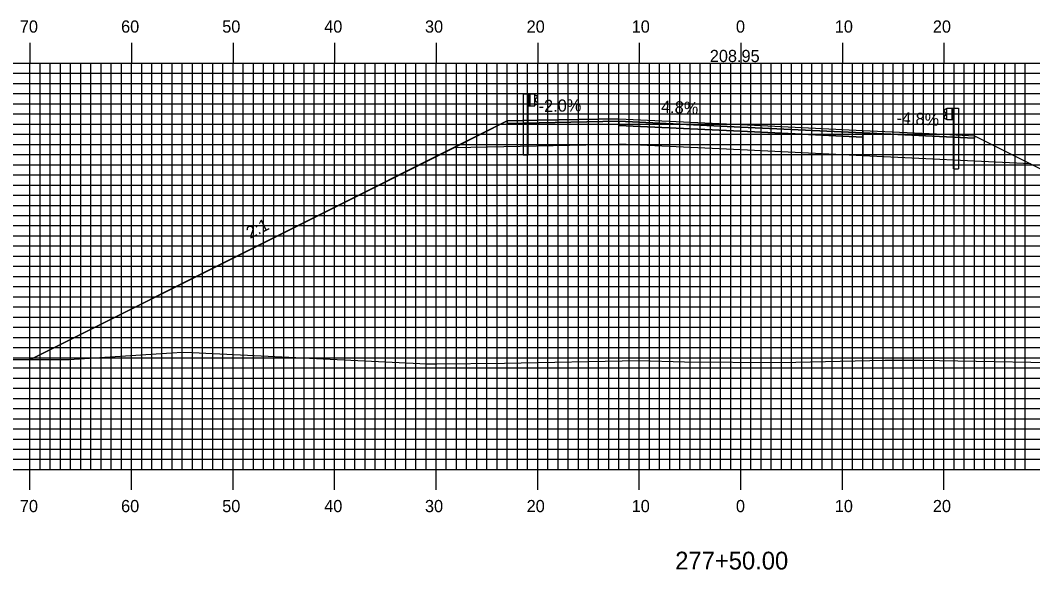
# Model space of a CAD drawing. Extents: x 1810193 to 1810536, y 442591 to 442811.
# Drawn here: x 1810287.9 to 1810387.6, y 442658.8 to 442712.9 of the extents above; entities that cross this region are included whole.
import ezdxf

# ---------------------------------------------------------------- set-up
doc = ezdxf.new("R2010")
doc.units = 0
for name, color, linetype in [('ANNOTATION', 7, 'Continuous'), ('D_Guardrail_Beam_Lt', 7, 'Continuous'), ('D_Guardrail_Beam_Rt', 7, 'Continuous'), ('D_Roadway_Centerline', 7, 'Continuous'), ('D_Roadway_Centerline_Text', 7, 'Continuous'), ('D_Roadway_Edge_Shoulder', 7, 'Continuous'), ('D_Roadway_Edge_TW', 7, 'Continuous'), ('D_Roadway_Pavement', 7, 'Continuous'), ('D_Roadway_SlopeLines', 7, 'Continuous'), ('D_Roadway_SubGrade', 7, 'Continuous'), ('H_V ANNOTATION', 7, 'Continuous'), ('MAJOR', 7, 'Continuous'), ('MINOR', 7, 'Continuous'), ('S_Roadway_Centerline', 7, 'Continuous')]:
    doc.layers.add(name, color=color, linetype=linetype)

msp = doc.modelspace()

# ---------------------------------------------------------------- linework, layer by layer
at = {"layer": 'D_Guardrail_Beam_Lt'}
for p, q in [((1810337.434, 442705.62), (1810337.434, 442699.62)), ((1810337.905, 442705.62), (1810337.434, 442705.62)), ((1810338.593, 442705.62), (1810337.905, 442705.62)), ((1810337.905, 442705.62), (1810337.905, 442704.453)), ((1810337.968, 442705.62), (1810337.968, 442704.453)), ((1810338.072, 442705.62), (1810338.072, 442704.453)), ((1810338.593, 442704.453), (1810338.593, 442705.62)), ((1810338.593, 442705.536), (1810338.667, 442705.522)), ((1810338.597, 442705.071), (1810338.597, 442705.001)), ((1810338.826, 442705.272), (1810338.631, 442705.136)), ((1810338.631, 442704.937), (1810338.826, 442704.801)), ((1810338.683, 442705.515), (1810338.826, 442705.415)), ((1810337.905, 442704.453), (1810338.593, 442704.453)), ((1810337.926, 442699.62), (1810337.926, 442704.453)), ((1810338.667, 442704.551), (1810338.593, 442704.536)), ((1810338.826, 442704.657), (1810338.683, 442704.557)), ((1810337.926, 442699.62), (1810337.434, 442699.62))]:
    msp.add_line(p, q, dxfattribs=at)
for centre, major_axis, start_param, end_param in [((1810338.676, 442705.071), (-0.0789, 0), 5.323254, 6.283185), ((1810338.676, 442705.001), (-0.0789, 0), 6.283185, 7.243116), ((1810338.659, 442705.481), (0.0417, 0), 0.959931, 1.376053), ((1810338.776, 442705.343), (0.0877, 0), 5.323254, 7.243116), ((1810338.776, 442704.729), (0.0877, 0), 5.323254, 7.243116), ((1810338.659, 442704.591), (0.0417, 0), 4.907132, 5.323254)]:
    msp.add_ellipse(centre, major_axis=major_axis, ratio=0.995501, start_param=start_param, end_param=end_param, dxfattribs=at)
at = {"layer": 'D_Guardrail_Beam_Rt'}
for p, q in [((1810379.044, 442704.139), (1810378.901, 442704.039)), ((1810378.901, 442703.896), (1810379.096, 442703.76)), ((1810379.134, 442704.16), (1810379.06, 442704.146)), ((1810379.134, 442704.244), (1810379.822, 442704.244)), ((1810379.134, 442703.077), (1810379.134, 442704.244)), ((1810379.655, 442704.244), (1810379.655, 442703.077)), ((1810379.759, 442704.244), (1810379.759, 442703.077)), ((1810379.822, 442704.244), (1810380.293, 442704.244)), ((1810379.822, 442704.244), (1810379.822, 442703.077)), ((1810380.293, 442704.244), (1810380.293, 442698.244)), ((1810379.096, 442703.561), (1810378.901, 442703.425)), ((1810378.901, 442703.281), (1810379.044, 442703.181)), ((1810379.06, 442703.175), (1810379.134, 442703.16)), ((1810379.13, 442703.695), (1810379.13, 442703.625)), ((1810379.822, 442703.077), (1810379.134, 442703.077)), ((1810379.801, 442698.244), (1810379.801, 442703.077)), ((1810379.801, 442698.244), (1810380.293, 442698.244))]:
    msp.add_line(p, q, dxfattribs=at)
for centre, major_axis, start_param, end_param in [((1810378.951, 442703.967), (-0.0877, 0), 5.323254, 7.243116), ((1810379.068, 442704.105), (-0.0417, 0), 4.907132, 5.323254), ((1810379.051, 442703.695), (0.0789, 0), 0, 0.959931), ((1810378.951, 442703.353), (-0.0877, 0), 5.323254, 7.243116), ((1810379.068, 442703.215), (-0.0417, 0), 0.959931, 1.376053), ((1810379.051, 442703.625), (0.0789, 0), 5.323254, 6.283185)]:
    msp.add_ellipse(centre, major_axis=major_axis, ratio=0.995501, start_param=start_param, end_param=end_param, dxfattribs=at)
at = {"layer": 'D_Roadway_Centerline'}
msp.add_lwpolyline([(1810288.916, 442679.503), (1810330.655, 442700.372), (1810335.863, 442702.976), (1810338.863, 442703.036), (1810346.863, 442703.196), (1810358.863, 442702.62), (1810370.863, 442702.044), (1810378.863, 442701.66), (1810381.863, 442701.516), (1810387.395, 442698.751), (1810427.355, 442678.771)], dxfattribs=at)
at = {"layer": 'D_Roadway_Edge_Shoulder'}
for points in [[(1810346.863, 442703.196), (1810338.863, 442703.036), (1810338.863, 442703.036), (1810335.863, 442702.976), (1810335.863, 442702.726), (1810346.863, 442702.946)], [(1810370.863, 442702.044), (1810378.863, 442701.66), (1810378.863, 442701.66), (1810381.863, 442701.516), (1810381.863, 442701.266), (1810370.863, 442701.794)]]:
    msp.add_lwpolyline(points, close=True, dxfattribs=at)
at = {"layer": 'D_Roadway_Edge_TW'}
msp.add_lwpolyline([(1810346.863, 442702.946), (1810346.863, 442703.196), (1810358.863, 442702.62), (1810370.863, 442702.044), (1810370.863, 442701.794), (1810358.863, 442702.37)], close=True, dxfattribs=at)
at = {"layer": 'D_Roadway_Pavement'}
msp.add_lwpolyline([(1810346.863, 442702.53), (1810346.863, 442702.946), (1810358.863, 442702.37), (1810370.863, 442701.794), (1810370.863, 442701.378), (1810358.863, 442701.954)], close=True, dxfattribs=at)
for points in [[(1810346.863, 442702.946), (1810346.863, 442702.53)], [(1810370.863, 442701.794), (1810370.863, 442701.378)]]:
    msp.add_lwpolyline(points, dxfattribs=at)
at = {"layer": 'D_Roadway_SlopeLines'}
for points in [[(1810335.863, 442702.976), (1810288.916, 442679.503)], [(1810381.863, 442701.516), (1810427.355, 442678.771)]]:
    msp.add_lwpolyline(points, dxfattribs=at)
at = {"layer": 'D_Roadway_SubGrade'}
for points in [[(1810346.863, 442702.53), (1810346.863, 442702.946), (1810335.863, 442702.726), (1810335.863, 442702.976), (1810330.655, 442700.372), (1810346.863, 442700.696)], [(1810346.863, 442700.696), (1810346.863, 442702.946), (1810346.863, 442702.53), (1810358.863, 442701.954), (1810370.863, 442701.378), (1810370.863, 442701.794), (1810370.863, 442699.544), (1810358.863, 442700.12)], [(1810370.863, 442701.378), (1810370.863, 442701.794), (1810381.863, 442701.266), (1810381.863, 442701.516), (1810387.395, 442698.751), (1810370.863, 442699.544)]]:
    msp.add_lwpolyline(points, close=True, dxfattribs=at)
at = {"layer": 'MAJOR'}
for p, q in [((1810288.863, 442710.669), (1810288.863, 442708.665)), ((1810298.863, 442710.669), (1810298.863, 442708.665)), ((1810308.863, 442710.669), (1810308.863, 442708.665)), ((1810318.863, 442710.669), (1810318.863, 442708.665)), ((1810328.863, 442710.669), (1810328.863, 442708.665)), ((1810338.863, 442710.669), (1810338.863, 442708.665)), ((1810348.863, 442710.669), (1810348.863, 442708.665)), ((1810358.863, 442710.669), (1810358.863, 442708.665)), ((1810368.863, 442710.669), (1810368.863, 442708.665)), ((1810378.863, 442710.669), (1810378.863, 442708.665)), ((1810218.863, 442708.665), (1810498.863, 442708.665)), ((1810218.863, 442708.665), (1810498.863, 442708.665)), ((1810288.863, 442668.665), (1810288.863, 442708.665)), ((1810298.863, 442668.665), (1810298.863, 442708.665)), ((1810308.863, 442668.665), (1810308.863, 442708.665)), ((1810318.863, 442668.665), (1810318.863, 442708.665)), ((1810328.863, 442668.665), (1810328.863, 442708.665)), ((1810338.863, 442668.665), (1810338.863, 442708.665)), ((1810348.863, 442668.665), (1810348.863, 442708.665)), ((1810358.863, 442668.665), (1810358.863, 442708.665)), ((1810368.863, 442668.665), (1810368.863, 442708.665)), ((1810378.863, 442668.665), (1810378.863, 442708.665)), ((1810218.863, 442703.665), (1810498.863, 442703.665)), ((1810218.863, 442698.665), (1810498.863, 442698.665)), ((1810218.863, 442693.665), (1810498.863, 442693.665)), ((1810218.863, 442688.665), (1810498.863, 442688.665)), ((1810218.863, 442683.665), (1810498.863, 442683.665)), ((1810218.863, 442678.665), (1810498.863, 442678.665)), ((1810218.863, 442673.665), (1810498.863, 442673.665)), ((1810218.863, 442668.665), (1810498.863, 442668.665)), ((1810218.863, 442668.665), (1810498.863, 442668.665)), ((1810288.863, 442666.661), (1810288.863, 442668.665)), ((1810298.863, 442666.661), (1810298.863, 442668.665)), ((1810308.863, 442666.661), (1810308.863, 442668.665)), ((1810318.863, 442666.661), (1810318.863, 442668.665)), ((1810328.863, 442666.661), (1810328.863, 442668.665)), ((1810338.863, 442666.661), (1810338.863, 442668.665)), ((1810348.863, 442666.661), (1810348.863, 442668.665)), ((1810358.863, 442666.661), (1810358.863, 442668.665)), ((1810368.863, 442666.661), (1810368.863, 442668.665)), ((1810378.863, 442666.661), (1810378.863, 442668.665))]:
    msp.add_line(p, q, dxfattribs=at)
at = {"layer": 'MINOR'}
for p, q in [((1810289.863, 442668.665), (1810289.863, 442708.665)), ((1810290.863, 442668.665), (1810290.863, 442708.665)), ((1810291.863, 442668.665), (1810291.863, 442708.665)), ((1810292.863, 442668.665), (1810292.863, 442708.665)), ((1810293.863, 442668.665), (1810293.863, 442708.665)), ((1810294.863, 442668.665), (1810294.863, 442708.665)), ((1810295.863, 442668.665), (1810295.863, 442708.665)), ((1810296.863, 442668.665), (1810296.863, 442708.665)), ((1810297.863, 442668.665), (1810297.863, 442708.665)), ((1810299.863, 442668.665), (1810299.863, 442708.665)), ((1810300.863, 442668.665), (1810300.863, 442708.665)), ((1810301.863, 442668.665), (1810301.863, 442708.665)), ((1810302.863, 442668.665), (1810302.863, 442708.665)), ((1810303.863, 442668.665), (1810303.863, 442708.665)), ((1810304.863, 442668.665), (1810304.863, 442708.665)), ((1810305.863, 442668.665), (1810305.863, 442708.665)), ((1810306.863, 442668.665), (1810306.863, 442708.665)), ((1810307.863, 442668.665), (1810307.863, 442708.665)), ((1810309.863, 442668.665), (1810309.863, 442708.665)), ((1810310.863, 442668.665), (1810310.863, 442708.665)), ((1810311.863, 442668.665), (1810311.863, 442708.665)), ((1810312.863, 442668.665), (1810312.863, 442708.665)), ((1810313.863, 442668.665), (1810313.863, 442708.665)), ((1810314.863, 442668.665), (1810314.863, 442708.665)), ((1810315.863, 442668.665), (1810315.863, 442708.665)), ((1810316.863, 442668.665), (1810316.863, 442708.665)), ((1810317.863, 442668.665), (1810317.863, 442708.665)), ((1810319.863, 442668.665), (1810319.863, 442708.665)), ((1810320.863, 442668.665), (1810320.863, 442708.665)), ((1810321.863, 442668.665), (1810321.863, 442708.665)), ((1810322.863, 442668.665), (1810322.863, 442708.665)), ((1810323.863, 442668.665), (1810323.863, 442708.665)), ((1810324.863, 442668.665), (1810324.863, 442708.665)), ((1810325.863, 442668.665), (1810325.863, 442708.665)), ((1810326.863, 442668.665), (1810326.863, 442708.665)), ((1810327.863, 442668.665), (1810327.863, 442708.665)), ((1810329.863, 442668.665), (1810329.863, 442708.665)), ((1810330.863, 442668.665), (1810330.863, 442708.665)), ((1810331.863, 442668.665), (1810331.863, 442708.665)), ((1810332.863, 442668.665), (1810332.863, 442708.665)), ((1810333.863, 442668.665), (1810333.863, 442708.665)), ((1810334.863, 442668.665), (1810334.863, 442708.665)), ((1810335.863, 442668.665), (1810335.863, 442708.665)), ((1810336.863, 442668.665), (1810336.863, 442708.665)), ((1810337.863, 442668.665), (1810337.863, 442708.665)), ((1810339.863, 442668.665), (1810339.863, 442708.665)), ((1810340.863, 442668.665), (1810340.863, 442708.665)), ((1810341.863, 442668.665), (1810341.863, 442708.665)), ((1810342.863, 442668.665), (1810342.863, 442708.665)), ((1810343.863, 442668.665), (1810343.863, 442708.665)), ((1810344.863, 442668.665), (1810344.863, 442708.665)), ((1810345.863, 442668.665), (1810345.863, 442708.665)), ((1810346.863, 442668.665), (1810346.863, 442708.665)), ((1810347.863, 442668.665), (1810347.863, 442708.665)), ((1810349.863, 442668.665), (1810349.863, 442708.665)), ((1810350.863, 442668.665), (1810350.863, 442708.665)), ((1810351.863, 442668.665), (1810351.863, 442708.665)), ((1810352.863, 442668.665), (1810352.863, 442708.665)), ((1810353.863, 442668.665), (1810353.863, 442708.665)), ((1810354.863, 442668.665), (1810354.863, 442708.665)), ((1810355.863, 442668.665), (1810355.863, 442708.665)), ((1810356.863, 442668.665), (1810356.863, 442708.665)), ((1810357.863, 442668.665), (1810357.863, 442708.665)), ((1810359.863, 442668.665), (1810359.863, 442708.665)), ((1810360.863, 442668.665), (1810360.863, 442708.665)), ((1810361.863, 442668.665), (1810361.863, 442708.665)), ((1810362.863, 442668.665), (1810362.863, 442708.665)), ((1810363.863, 442668.665), (1810363.863, 442708.665)), ((1810364.863, 442668.665), (1810364.863, 442708.665)), ((1810365.863, 442668.665), (1810365.863, 442708.665)), ((1810366.863, 442668.665), (1810366.863, 442708.665)), ((1810367.863, 442668.665), (1810367.863, 442708.665)), ((1810369.863, 442668.665), (1810369.863, 442708.665)), ((1810370.863, 442668.665), (1810370.863, 442708.665)), ((1810371.863, 442668.665), (1810371.863, 442708.665)), ((1810372.863, 442668.665), (1810372.863, 442708.665)), ((1810373.863, 442668.665), (1810373.863, 442708.665)), ((1810374.863, 442668.665), (1810374.863, 442708.665)), ((1810375.863, 442668.665), (1810375.863, 442708.665)), ((1810376.863, 442668.665), (1810376.863, 442708.665)), ((1810377.863, 442668.665), (1810377.863, 442708.665)), ((1810379.863, 442668.665), (1810379.863, 442708.665)), ((1810380.863, 442668.665), (1810380.863, 442708.665)), ((1810381.863, 442668.665), (1810381.863, 442708.665)), ((1810382.863, 442668.665), (1810382.863, 442708.665)), ((1810383.863, 442668.665), (1810383.863, 442708.665)), ((1810384.863, 442668.665), (1810384.863, 442708.665)), ((1810385.863, 442668.665), (1810385.863, 442708.665)), ((1810386.863, 442668.665), (1810386.863, 442708.665)), ((1810218.863, 442707.665), (1810498.863, 442707.665)), ((1810218.863, 442706.665), (1810498.863, 442706.665)), ((1810218.863, 442705.665), (1810498.863, 442705.665)), ((1810218.863, 442704.665), (1810498.863, 442704.665)), ((1810218.863, 442702.665), (1810498.863, 442702.665)), ((1810218.863, 442701.665), (1810498.863, 442701.665)), ((1810218.863, 442700.665), (1810498.863, 442700.665)), ((1810218.863, 442699.665), (1810498.863, 442699.665)), ((1810218.863, 442697.665), (1810498.863, 442697.665)), ((1810218.863, 442696.665), (1810498.863, 442696.665)), ((1810218.863, 442695.665), (1810498.863, 442695.665)), ((1810218.863, 442694.665), (1810498.863, 442694.665)), ((1810218.863, 442692.665), (1810498.863, 442692.665)), ((1810218.863, 442691.665), (1810498.863, 442691.665)), ((1810218.863, 442690.665), (1810498.863, 442690.665)), ((1810218.863, 442689.665), (1810498.863, 442689.665)), ((1810218.863, 442687.665), (1810498.863, 442687.665)), ((1810218.863, 442686.665), (1810498.863, 442686.665)), ((1810218.863, 442685.665), (1810498.863, 442685.665)), ((1810218.863, 442684.665), (1810498.863, 442684.665)), ((1810218.863, 442682.665), (1810498.863, 442682.665)), ((1810218.863, 442681.665), (1810498.863, 442681.665)), ((1810218.863, 442680.665), (1810498.863, 442680.665)), ((1810218.863, 442679.665), (1810498.863, 442679.665)), ((1810218.863, 442677.665), (1810498.863, 442677.665)), ((1810218.863, 442676.665), (1810498.863, 442676.665)), ((1810218.863, 442675.665), (1810498.863, 442675.665)), ((1810218.863, 442674.665), (1810498.863, 442674.665)), ((1810218.863, 442672.665), (1810498.863, 442672.665)), ((1810218.863, 442671.665), (1810498.863, 442671.665)), ((1810218.863, 442670.665), (1810498.863, 442670.665)), ((1810218.863, 442669.665), (1810498.863, 442669.665))]:
    msp.add_line(p, q, dxfattribs=at)
at = {"layer": 'S_Roadway_Centerline'}
msp.add_lwpolyline([(1810218.863, 442679.332), (1810223.523, 442679.457), (1810232.549, 442679.313), (1810235.549, 442679.241), (1810238.398, 442679.29), (1810255.314, 442679.168), (1810259.948, 442679.217), (1810269.89, 442679.529), (1810279.08, 442679.526), (1810281.568, 442679.506), (1810292.735, 442679.501), (1810302.786, 442680.159), (1810303.87, 442680.202), (1810304.849, 442680.189), (1810327.958, 442679.074), (1810328.938, 442679.078), (1810335.583, 442679.137), (1810348.835, 442679.401), (1810353.3, 442679.268), (1810362.8, 442679.181), (1810373.055, 442679.415), (1810374.702, 442679.438), (1810376.616, 442679.441), (1810394.657, 442679.113)], dxfattribs=at)

# ---------------------------------------------------------------- texts
at = {"layer": 'ANNOTATION'}
for s, rotation, p in [('-2.0%', 1.14576, (1810338.97, 442703.839)), ('4.8%', 357.25191, (1810350.993, 442703.8)), ('-4.8%', 357.25191, (1810374.172, 442702.688)), ('2:1', 26.56505, (1810310.535, 442691.348))]:
    msp.add_text(s, height=1.2, rotation=rotation, dxfattribs=at).set_placement(p)
at = {"layer": 'D_Roadway_Centerline'}
for s, p in [('C', (1810358.858, 442702.62)), ('L', (1810358.863, 442702.613))]:
    msp.add_text(s, height=0.0146, dxfattribs=at).set_placement(p)
at = {"layer": 'D_Roadway_Centerline_Text'}
msp.add_text('208.95', height=1.2, dxfattribs=at).set_placement((1810355.808, 442708.768))
at = {"layer": 'H_V ANNOTATION'}
for s, height, p in [('70', 1.2, (1810287.868, 442711.665)), ('60', 1.2, (1810297.836, 442711.665)), ('50', 1.2, (1810307.793, 442711.665)), ('40', 1.2, (1810317.836, 442711.665)), ('30', 1.2, (1810327.761, 442711.665)), ('20', 1.2, (1810337.771, 442711.665)), ('10', 1.2, (1810348.114, 442711.665)), ('0', 1.2, (1810358.382, 442711.665)), ('10', 1.2, (1810368.114, 442711.665)), ('20', 1.2, (1810377.771, 442711.665)), ('70', 1.2, (1810287.868, 442664.465)), ('60', 1.2, (1810297.836, 442664.465)), ('50', 1.2, (1810307.793, 442664.465)), ('40', 1.2, (1810317.836, 442664.465)), ('30', 1.2, (1810327.761, 442664.465)), ('20', 1.2, (1810337.771, 442664.465)), ('10', 1.2, (1810348.114, 442664.465)), ('0', 1.2, (1810358.382, 442664.465)), ('10', 1.2, (1810368.114, 442664.465)), ('20', 1.2, (1810377.771, 442664.465)), ('277+50.00', 1.75, (1810352.402, 442658.821))]:
    msp.add_text(s, height=height, dxfattribs=at).set_placement(p)

doc.saveas('drawing.dxf')
